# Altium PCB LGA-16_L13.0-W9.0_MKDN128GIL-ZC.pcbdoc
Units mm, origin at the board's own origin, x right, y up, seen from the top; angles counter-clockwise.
Board outline 26.2 x 21.76 mm, 2 copper layers (Top Layer, Bottom Layer), stack 0 mm thick; 1 components, 0 nets, 20 pads, 0 vias.
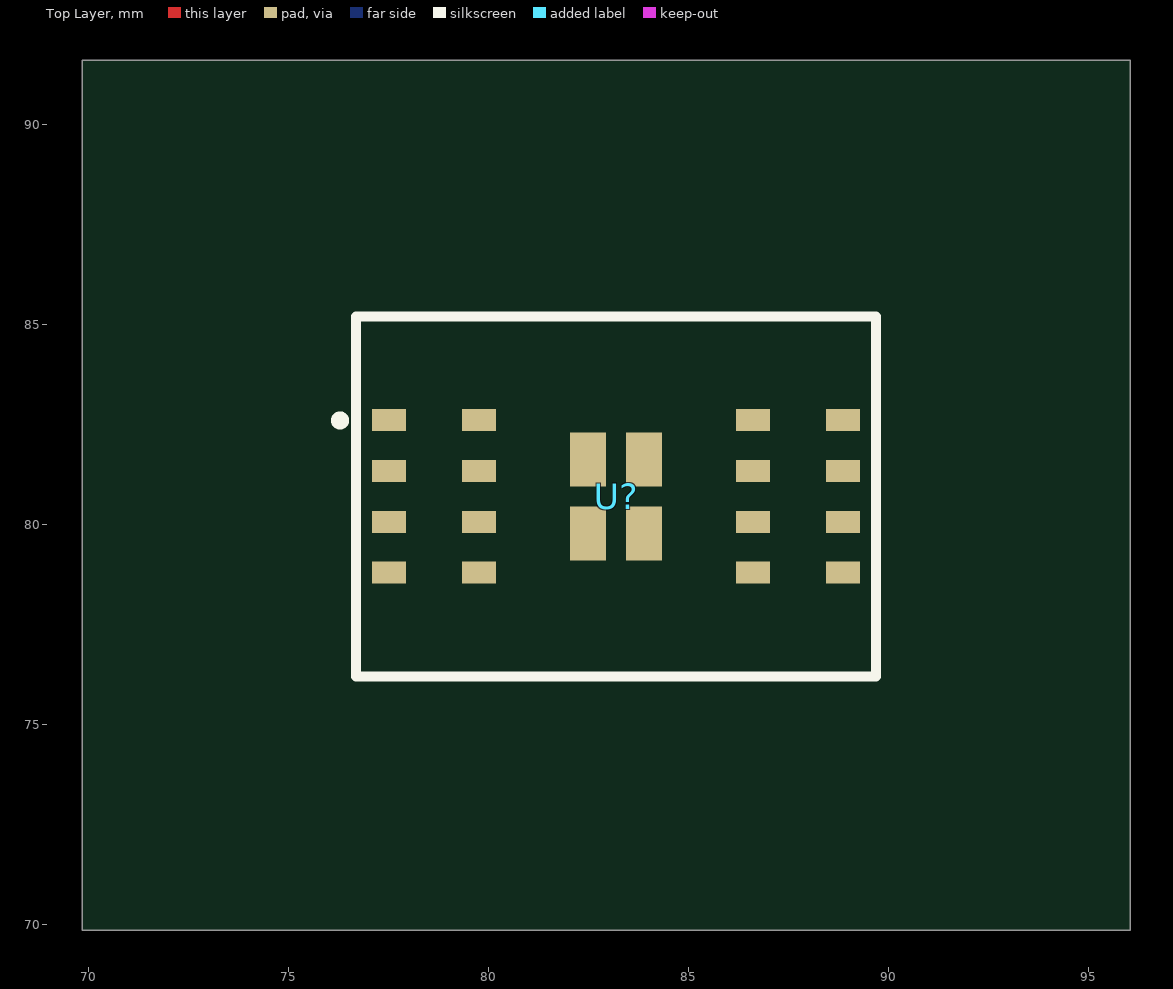
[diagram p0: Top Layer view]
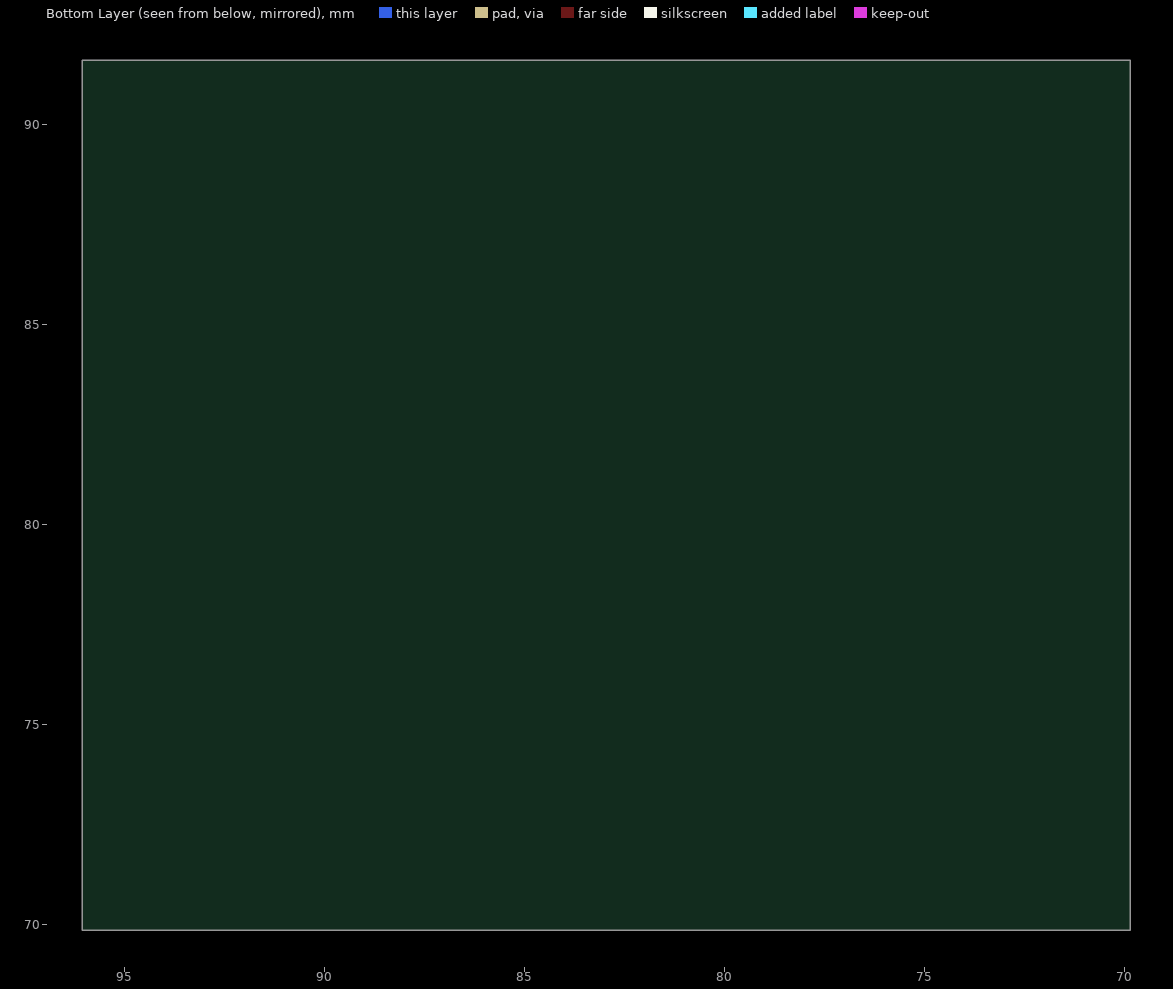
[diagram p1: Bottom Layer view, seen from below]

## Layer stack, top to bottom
Top Layer: signal copper (thickness not stored)
Bottom Layer: signal copper (thickness not stored)

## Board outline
96.05,69.85 69.85,69.85 69.85,91.61 96.05,91.61

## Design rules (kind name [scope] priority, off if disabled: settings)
PasteMaskExpansion "Paste Mask Expansion" [All] p1: expansion=0
SolderMaskExpansion "Solder Mask Expansion" [IsVia] p1: expansion=-25.4 istentingtop=TRUE
SolderMaskExpansion "Solder Mask Expansion" [All] p2: expansion=0.051 istentingtop=FALSE

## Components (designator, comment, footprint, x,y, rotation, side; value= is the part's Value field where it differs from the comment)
U? "" LGA-16_L13.0-W9.0_MKDN128GIL-ZC 83.2,80.7 r0 top

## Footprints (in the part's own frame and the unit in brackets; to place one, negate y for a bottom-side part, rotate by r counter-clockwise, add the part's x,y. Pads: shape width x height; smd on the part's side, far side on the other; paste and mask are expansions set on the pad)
LGA-16_L13.0-W9.0_MKDN128GIL-ZC [mm]
  rect 0.85x0.55 smd: 1(-5.675,1.905) 2(-5.675,0.635) 3(-5.675,-0.635) 4(-5.675,-1.905) 5(-3.425,1.905) 6(-3.425,0.635) 7(-3.425,-0.635) 8(-3.425,-1.905) 9(3.425,1.905) 10(3.425,0.635) 11(3.425,-0.635) 12(3.425,-1.905) 13(5.675,1.905) 14(5.675,0.635) 15(5.675,-0.635) 16(5.675,-1.905)
  rect 0.9x1.35 smd: 17(-0.7,-0.925) 17(-0.7,0.925) 17(0.7,-0.925) 17(0.7,0.925)
  silkscreen extent -7,-4.5 6.5,4.5

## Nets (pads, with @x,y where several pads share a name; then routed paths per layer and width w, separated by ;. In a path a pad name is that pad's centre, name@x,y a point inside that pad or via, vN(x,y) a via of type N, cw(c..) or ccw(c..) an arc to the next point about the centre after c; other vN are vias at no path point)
pads on no net: U?.1 U?.2 U?.3 U?.4 U?.5 U?.6 U?.7 U?.8 U?.9 U?.10 U?.11 U?.12 U?.13 U?.14 U?.15 U?.16 U?.17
